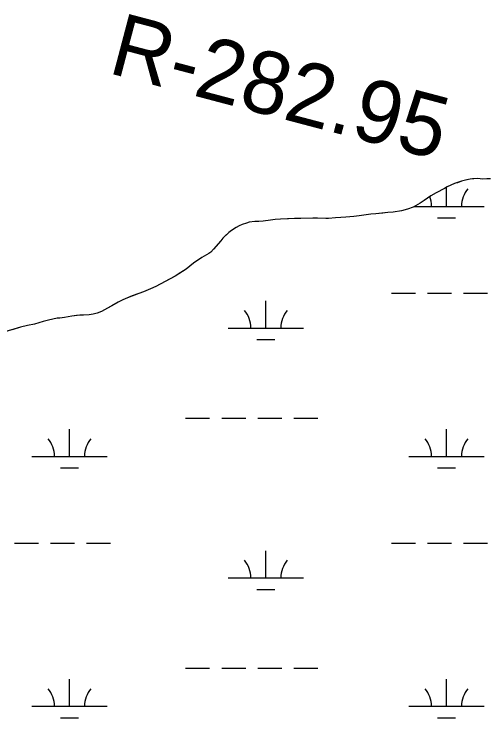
# Model space of a CAD drawing. Extents: x 3192927 to 3230760, y 831141 to 856475.
# Drawn here: x 3214052 to 3214685, y 837063 to 838000 of the extents above; entities that cross this region are included whole.
import ezdxf

# ---------------------------------------------------------------- set-up
doc = ezdxf.new("R2010")
doc.units = 0
for name, color, linetype in [('V-RIVR-RANG-IDEN', 7, 'Continuous'), ('V-SITE-VEGE', 7, 'Continuous'), ('V-TOPO-SHOR', 7, 'Continuous'), ('V-WETL-SWMP', 7, 'Continuous')]:
    doc.layers.add(name, color=color, linetype=linetype)

msp = doc.modelspace()

# ---------------------------------------------------------------- linework, layer by layer
at = {"layer": 'V-SITE-VEGE'}
for p, q in [((3214659.69, 837780.35), (3214651.71, 837778.31)), ((3214669.48, 837781.01), (3214659.69, 837780.35)), ((3214675.88, 837780.25), (3214669.48, 837781.01)), ((3214686.47, 837780.71), (3214675.88, 837780.25)), ((3214629.17, 837769.79), (3214625.39, 837767.57)), ((3214638.94, 837774.24), (3214629.17, 837769.79)), ((3214648.11, 837777.29), (3214638.94, 837774.24)), ((3214651.71, 837778.31), (3214648.11, 837777.29)), ((3214614.23, 837761.91), (3214607.06, 837758.07)), ((3214625.39, 837767.57), (3214614.23, 837761.91)), ((3214598.5, 837751.62), (3214592.92, 837748)), ((3214602.68, 837755.05), (3214598.5, 837751.62)), ((3214607.06, 837758.07), (3214602.68, 837755.05)), ((3214583.56, 837742.75), (3214576.18, 837740.11)), ((3214592.92, 837748), (3214583.56, 837742.75)), ((3214527.45, 837733.43), (3214518.27, 837732.18)), ((3214533.85, 837733.87), (3214527.45, 837733.43)), ((3214550.22, 837735.76), (3214533.85, 837733.87)), ((3214557.02, 837736.4), (3214550.22, 837735.76)), ((3214568, 837738.06), (3214557.02, 837736.4)), ((3214576.18, 837740.11), (3214568, 837738.06)), ((3214372.82, 837723.76), (3214365.63, 837722.72)), ((3214378.22, 837723.99), (3214372.82, 837723.76)), ((3214384.01, 837724.42), (3214378.22, 837723.99)), ((3214394, 837725.48), (3214384.01, 837724.42)), ((3214400.19, 837726.31), (3214394, 837725.48)), ((3214406.98, 837726.95), (3214400.19, 837726.31)), ((3214425.56, 837727.66), (3214406.98, 837726.95)), ((3214434.16, 837727.7), (3214425.56, 837727.66)), ((3214456.33, 837728.43), (3214434.16, 837727.7)), ((3214467.53, 837727.9), (3214456.33, 837728.43)), ((3214471.13, 837727.92), (3214467.53, 837727.9)), ((3214480.51, 837728.77), (3214471.13, 837727.92)), ((3214493.9, 837729.64), (3214480.51, 837728.77)), ((3214504.89, 837730.51), (3214493.9, 837729.64)), ((3214511.68, 837731.15), (3214504.89, 837730.51)), ((3214518.27, 837732.18), (3214511.68, 837731.15)), ((3214348.09, 837715.82), (3214342.11, 837711.99)), ((3214352.27, 837718.05), (3214348.09, 837715.82)), ((3214356.06, 837719.67), (3214352.27, 837718.05)), ((3214361.84, 837721.7), (3214356.06, 837719.67)), ((3214365.63, 837722.72), (3214361.84, 837721.7)), ((3214338.53, 837708.97), (3214330.18, 837701.53)), ((3214342.11, 837711.99), (3214338.53, 837708.97)), ((3214327.6, 837698.12), (3214318.07, 837687.07)), ((3214330.18, 837701.53), (3214327.6, 837698.12)), ((3214318.07, 837687.07), (3214314.3, 837683.06)), ((3214311.91, 837681.04), (3214302.55, 837675.79)), ((3214314.3, 837683.06), (3214311.91, 837681.04)), ((3214291.4, 837668.54), (3214281.65, 837660.28)), ((3214302.55, 837675.79), (3214291.4, 837668.54)), ((3214281.65, 837660.28), (3214267.11, 837651.21)), ((3214267.11, 837651.21), (3214241.21, 837637.07)), ((3214224.86, 837630.19), (3214218.68, 837628.15)), ((3214234.24, 837634.04), (3214224.86, 837630.19)), ((3214241.21, 837637.07), (3214234.24, 837634.04)), ((3214203.53, 837622.27), (3214197.35, 837619.44)), ((3214218.68, 837628.15), (3214203.53, 837622.27)), ((3214191.17, 837616.4), (3214177.02, 837608.33)), ((3214197.35, 837619.44), (3214191.17, 837616.4)), ((3214163.07, 837601.65), (3214157.88, 837600.62)), ((3214168.66, 837603.88), (3214163.07, 837601.65)), ((3214177.02, 837608.33), (3214168.66, 837603.88)), ((3214098.17, 837592.49), (3214091.39, 837590.85)), ((3214109.75, 837594.96), (3214098.17, 837592.49)), ((3214113.35, 837594.97), (3214109.75, 837594.96)), ((3214119.74, 837595.81), (3214113.35, 837594.97)), ((3214124.53, 837596.83), (3214119.74, 837595.81)), ((3214129.32, 837597.66), (3214124.53, 837596.83)), ((3214140.1, 837599.12), (3214129.32, 837597.66)), ((3214144.7, 837599.15), (3214140.1, 837599.12)), ((3214152.49, 837599.79), (3214144.7, 837599.15)), ((3214157.88, 837600.62), (3214152.49, 837599.79)), ((3214061.05, 837583.29), (3214040.11, 837576.77)), ((3214070.23, 837585.53), (3214061.05, 837583.29)), ((3214079.62, 837587.19), (3214070.23, 837585.53)), ((3214091.39, 837590.85), (3214079.62, 837587.19))]:
    msp.add_line(p, q, dxfattribs=at)
at = {"layer": 'V-TOPO-SHOR'}
for points in [[(3214686.47, 837780.71), (3214681.67, 837780.48), (3214675.88, 837780.25), (3214672.88, 837780.63), (3214669.48, 837781.01), (3214662.89, 837780.57), (3214659.69, 837780.35), (3214655.1, 837779.13), (3214651.71, 837778.31), (3214648.11, 837777.29), (3214642.73, 837775.46), (3214638.94, 837774.24), (3214634.95, 837772.42), (3214629.17, 837769.79), (3214625.39, 837767.57), (3214621.8, 837765.75), (3214617.02, 837763.32), (3214614.23, 837761.91), (3214607.06, 837758.07), (3214602.68, 837755.05), (3214598.5, 837751.62), (3214592.92, 837748), (3214583.56, 837742.75), (3214576.18, 837740.11), (3214568, 837738.06), (3214557.02, 837736.4), (3214550.22, 837735.76), (3214543.44, 837734.92), (3214533.85, 837733.87), (3214527.45, 837733.43), (3214518.27, 837732.18), (3214511.68, 837731.15), (3214504.89, 837730.51), (3214493.9, 837729.64), (3214487.31, 837729.21), (3214480.51, 837728.77), (3214471.13, 837727.92), (3214467.53, 837727.9), (3214456.33, 837728.43), (3214450.14, 837728.2), (3214434.16, 837727.7)], [(3214434.16, 837727.7), (3214425.56, 837727.66), (3214417.77, 837727.41), (3214406.98, 837726.95), (3214400.19, 837726.31), (3214394, 837725.48), (3214384.01, 837724.42), (3214378.22, 837723.99), (3214372.82, 837723.76), (3214365.63, 837722.72), (3214361.84, 837721.7), (3214356.06, 837719.67), (3214352.27, 837718.05), (3214348.09, 837715.82), (3214342.11, 837711.99), (3214338.53, 837708.97), (3214333.56, 837704.55), (3214330.18, 837701.53), (3214327.6, 837698.12), (3214324.03, 837693.9), (3214318.07, 837687.07), (3214314.3, 837683.06), (3214311.91, 837681.04), (3214302.55, 837675.79), (3214291.4, 837668.54), (3214281.65, 837660.28), (3214274.48, 837655.85), (3214267.11, 837651.21), (3214259.34, 837646.97), (3214247.99, 837640.71), (3214241.21, 837637.07), (3214234.24, 837634.04), (3214224.86, 837630.19), (3214218.68, 837628.15), (3214209.71, 837624.7), (3214203.53, 837622.27), (3214197.35, 837619.44), (3214191.17, 837616.4), (3214182.8, 837611.56), (3214177.02, 837608.33), (3214168.66, 837603.88), (3214163.07, 837601.65), (3214157.88, 837600.62), (3214152.49, 837599.79), (3214144.7, 837599.15), (3214140.1, 837599.12), (3214135.71, 837598.5), (3214129.32, 837597.66), (3214124.53, 837596.83), (3214119.74, 837595.81), (3214113.35, 837594.97), (3214109.75, 837594.96), (3214098.17, 837592.49), (3214091.39, 837590.85), (3214079.62, 837587.19), (3214070.23, 837585.53), (3214061.05, 837583.29), (3214049.88, 837579.82)]]:
    msp.add_lwpolyline(points, dxfattribs=at)
at = {"layer": 'V-WETL-SWMP'}
for p, q in [((3214655.1, 837779.13), (3214651.71, 837778.31)), ((3214659.69, 837780.35), (3214655.1, 837779.13)), ((3214662.89, 837780.57), (3214659.69, 837780.35)), ((3214669.48, 837781.01), (3214662.89, 837780.57)), ((3214672.88, 837780.63), (3214669.48, 837781.01)), ((3214675.88, 837780.25), (3214672.88, 837780.63)), ((3214681.67, 837780.48), (3214675.88, 837780.25)), ((3214686.47, 837780.71), (3214681.67, 837780.48)), ((3214629.17, 837769.79), (3214625.39, 837767.57)), ((3214634.95, 837772.42), (3214629.17, 837769.79)), ((3214638.94, 837774.24), (3214634.95, 837772.42)), ((3214642.73, 837775.46), (3214638.94, 837774.24)), ((3214648.11, 837777.29), (3214642.73, 837775.46)), ((3214651.71, 837778.31), (3214648.11, 837777.29)), ((3214614.23, 837761.91), (3214607.05, 837758.07)), ((3214625.39, 837767.57), (3214614.23, 837761.91)), ((3214628.13, 837743.9), (3214628.13, 837769.17)), ((3214598.5, 837751.62), (3214592.92, 837748)), ((3214602.67, 837755.05), (3214598.5, 837751.62)), ((3214607.05, 837758.07), (3214602.67, 837755.05)), ((3214583.56, 837742.75), (3214576.18, 837740.11)), ((3214592.92, 837748), (3214583.56, 837742.75)), ((3214585.62, 837743.9), (3214678.13, 837743.9)), ((3214527.45, 837733.43), (3214518.27, 837732.18)), ((3214533.85, 837733.87), (3214527.45, 837733.43)), ((3214543.43, 837734.92), (3214533.85, 837733.87)), ((3214550.22, 837735.76), (3214543.43, 837734.92)), ((3214557.01, 837736.4), (3214550.22, 837735.76)), ((3214568, 837738.06), (3214557.01, 837736.4)), ((3214576.18, 837740.11), (3214568, 837738.06)), ((3214372.82, 837723.76), (3214365.63, 837722.72)), ((3214378.22, 837723.99), (3214372.82, 837723.76)), ((3214384.01, 837724.42), (3214378.22, 837723.99)), ((3214394, 837725.48), (3214384.01, 837724.42)), ((3214400.19, 837726.31), (3214394, 837725.48)), ((3214406.98, 837726.95), (3214400.19, 837726.31)), ((3214417.77, 837727.41), (3214406.98, 837726.95)), ((3214425.56, 837727.66), (3214417.77, 837727.41)), ((3214434.15, 837727.71), (3214425.56, 837727.66)), ((3214450.14, 837728.2), (3214434.15, 837727.71)), ((3214456.33, 837728.43), (3214450.14, 837728.2)), ((3214467.53, 837727.9), (3214456.33, 837728.43)), ((3214471.13, 837727.92), (3214467.53, 837727.9)), ((3214480.51, 837728.77), (3214471.13, 837727.92)), ((3214487.31, 837729.21), (3214480.51, 837728.77)), ((3214493.9, 837729.64), (3214487.31, 837729.21)), ((3214504.89, 837730.51), (3214493.9, 837729.64)), ((3214511.68, 837731.15), (3214504.89, 837730.51)), ((3214518.27, 837732.18), (3214511.68, 837731.15)), ((3214616.13, 837728.47), (3214640.13, 837728.47)), ((3214348.09, 837715.82), (3214342.11, 837711.99)), ((3214352.27, 837718.05), (3214348.09, 837715.82)), ((3214356.06, 837719.67), (3214352.27, 837718.05)), ((3214361.84, 837721.7), (3214356.06, 837719.67)), ((3214365.63, 837722.72), (3214361.84, 837721.7)), ((3214333.56, 837704.55), (3214330.18, 837701.53)), ((3214338.53, 837708.97), (3214333.56, 837704.55)), ((3214342.11, 837711.99), (3214338.53, 837708.97)), ((3214327.6, 837698.12), (3214324.03, 837693.9)), ((3214330.18, 837701.53), (3214327.6, 837698.12)), ((3214318.07, 837687.07), (3214314.3, 837683.06)), ((3214324.03, 837693.9), (3214318.07, 837687.07)), ((3214311.91, 837681.04), (3214302.55, 837675.79)), ((3214314.3, 837683.06), (3214311.91, 837681.04)), ((3214291.4, 837668.54), (3214281.65, 837660.29)), ((3214302.55, 837675.79), (3214291.4, 837668.54)), ((3214281.65, 837660.29), (3214274.48, 837655.85)), ((3214267.11, 837651.21), (3214259.34, 837646.97)), ((3214274.48, 837655.85), (3214267.11, 837651.21)), ((3214247.99, 837640.71), (3214241.21, 837637.07)), ((3214259.34, 837646.97), (3214247.99, 837640.71)), ((3214224.86, 837630.18), (3214218.68, 837628.15)), ((3214234.24, 837634.04), (3214224.86, 837630.18)), ((3214241.21, 837637.07), (3214234.24, 837634.04)), ((3214203.53, 837622.27), (3214197.35, 837619.44)), ((3214209.71, 837624.7), (3214203.53, 837622.27)), ((3214218.68, 837628.15), (3214209.71, 837624.7)), ((3214554.72, 837628.47), (3214586.72, 837628.47)), ((3214602.72, 837628.47), (3214634.72, 837628.47)), ((3214650.72, 837628.47), (3214682.72, 837628.47)), ((3214182.8, 837611.56), (3214177.02, 837608.33)), ((3214191.17, 837616.4), (3214182.8, 837611.56)), ((3214197.35, 837619.44), (3214191.17, 837616.4)), ((3214387.65, 837582.04), (3214387.65, 837618.04)), ((3214163.07, 837601.65), (3214157.88, 837600.62)), ((3214168.66, 837603.88), (3214163.07, 837601.65)), ((3214177.02, 837608.33), (3214168.66, 837603.88)), ((3214098.17, 837592.49), (3214091.39, 837590.85)), ((3214109.75, 837594.95), (3214098.17, 837592.49)), ((3214113.35, 837594.97), (3214109.75, 837594.95)), ((3214119.74, 837595.81), (3214113.35, 837594.97)), ((3214124.53, 837596.84), (3214119.74, 837595.81)), ((3214129.32, 837597.66), (3214124.53, 837596.84)), ((3214135.71, 837598.5), (3214129.32, 837597.66)), ((3214140.1, 837599.12), (3214135.71, 837598.5)), ((3214144.7, 837599.15), (3214140.1, 837599.12)), ((3214152.49, 837599.79), (3214144.7, 837599.15)), ((3214157.88, 837600.62), (3214152.49, 837599.79)), ((3214061.05, 837583.29), (3214049.88, 837579.82)), ((3214070.23, 837585.54), (3214061.05, 837583.29)), ((3214079.62, 837587.19), (3214070.23, 837585.54)), ((3214091.39, 837590.85), (3214079.62, 837587.19)), ((3214337.65, 837582.04), (3214437.65, 837582.04)), ((3214375.65, 837566.61), (3214399.65, 837566.61)), ((3214280.81, 837461.97), (3214312.81, 837461.97)), ((3214328.81, 837461.97), (3214360.81, 837461.97)), ((3214376.81, 837461.97), (3214408.81, 837461.97)), ((3214424.81, 837461.97), (3214456.81, 837461.97)), ((3214126.22, 837411.23), (3214126.22, 837447.23)), ((3214628.13, 837411.23), (3214628.13, 837447.23)), ((3214076.22, 837411.23), (3214176.22, 837411.23)), ((3214578.13, 837411.23), (3214678.13, 837411.23)), ((3214114.22, 837395.79), (3214138.22, 837395.79)), ((3214616.13, 837395.79), (3214640.13, 837395.79)), ((3214052.81, 837295.79), (3214084.81, 837295.79)), ((3214100.81, 837295.79), (3214132.81, 837295.79)), ((3214148.81, 837295.79), (3214180.81, 837295.79)), ((3214554.72, 837295.79), (3214586.72, 837295.79)), ((3214602.72, 837295.79), (3214634.72, 837295.79)), ((3214650.72, 837295.79), (3214682.72, 837295.79)), ((3214387.65, 837249.36), (3214387.65, 837285.36)), ((3214337.65, 837249.36), (3214437.65, 837249.36)), ((3214375.65, 837233.93), (3214399.65, 837233.93)), ((3214280.81, 837129.29), (3214312.81, 837129.29)), ((3214328.81, 837129.29), (3214360.81, 837129.29)), ((3214376.81, 837129.29), (3214408.81, 837129.29)), ((3214424.81, 837129.29), (3214456.81, 837129.29)), ((3214126.22, 837078.55), (3214126.22, 837114.55)), ((3214628.13, 837078.55), (3214628.13, 837114.55)), ((3214076.22, 837078.55), (3214176.22, 837078.55)), ((3214578.13, 837078.55), (3214678.13, 837078.55)), ((3214114.22, 837063.12), (3214138.22, 837063.12)), ((3214616.13, 837063.12), (3214640.13, 837063.12))]:
    msp.add_line(p, q, dxfattribs=at)
for centre, start, end in [((3214683.37, 837744.37), 139.22818, 180.77184), ((3214572.88, 837744.37), 359.22818, 21.25851), ((3214332.41, 837582.51), 359.22818, 40.77184), ((3214442.9, 837582.51), 139.22818, 180.77184), ((3214070.97, 837411.7), 359.22818, 40.77184), ((3214181.46, 837411.7), 139.22818, 180.77184), ((3214572.88, 837411.7), 359.22818, 40.77184), ((3214683.37, 837411.7), 139.22818, 180.77184), ((3214332.41, 837249.84), 359.22818, 40.77184), ((3214442.9, 837249.84), 139.22818, 180.77184), ((3214070.97, 837079.02), 359.22818, 40.77184), ((3214181.46, 837079.02), 139.22818, 180.77184), ((3214572.88, 837079.02), 359.22818, 40.77184), ((3214683.37, 837079.02), 139.22818, 180.77184)]:
    msp.add_arc(centre, 35.25, start, end, dxfattribs=at)

# ---------------------------------------------------------------- texts
at = {"layer": 'V-RIVR-RANG-IDEN'}
msp.add_text('R-282.95', height=83, rotation=345.22665, dxfattribs=at).set_placement((3214175.8, 837921.91))

doc.saveas('drawing.dxf')
